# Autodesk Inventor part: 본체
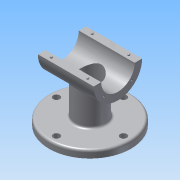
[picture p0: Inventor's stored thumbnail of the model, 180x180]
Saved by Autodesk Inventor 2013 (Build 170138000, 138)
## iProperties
Created: 2015-12
Part Number: 본체
Material: 알루미늄 6061
Document SubType Name: Modeling
Designer: mduedu
Density: 2.71 g/cm^3
Mass: 472.288 g
Surface Area: 460.057 cm^2
Volume: 174.276 cm^3
Author: mduedu
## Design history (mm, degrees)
sketch "스케치1"
  geometry: C1 r 55 at (0, 0); 1 further point
  constraints: 1 centre point, 1 coincident
  dimensions: "d124" = 110 diameter of C1
extrude "돌출1" new body sketch "스케치1" distance "d3" = 10; taper "d4" = 0 deg
sketch "스케치2"
  geometry: C1 r 32.5 at (80, 0); 1 further point
  constraints: 1 centre point, 1 horizontal alignment
  dimensions: "d5" = 65 diameter of C1; "d125" = 80 distance of C1.centre point (0, 0)
extrude "돌출2" join sketch "스케치2" stored distance "d7" = 75; taper "d8" = 0 deg
sketch "스케치3"
  geometry: C1 r 20 at (0, 0); 1 further point
  constraints: 1 centre point, 1 coincident
  dimensions: "d154" = 40 diameter of C1
extrude "돌출3" new body sketch "스케치3" stored distance "d12" = 75; taper "d13" = 0 deg
feature "결합1"
  node "솔리드2"
fillet "모깎기13" dims "d155" = 3
fillet "모깎기7" dims "d41" = 3
hole "구멍2" diameter "d44" = 45; stored, may be unused: countersink angle "d48" = 90 deg, drill point angle "d50" = 118 deg; dims "d42" = 10, "d43" = 10, "d45" = 6, "d46" = 4, "d47" = 2, "d49" = 8
sketch "스케치7" dims "d52" = 26.5
  geometry: L1 (0, 0)-(32.5, 0); L2 (0, 0)-(22.981, 22.981); A1 r 32.5 centre (0, 0) between (32.5, 0) and (22.981, 22.981) reference; 3 further points
  constraints: 4 end point, 2 point on circle, 1 coincident, 1 horizontal, 1 point on line, 3 other
  dimensions: "d51" = 45 deg angle of L2 L1
hole "구멍3" sketch "스케치7" at (18.738, 18.738) diameter "d54" = 2.459; stored, may be unused: countersink angle "d58" = 90 deg, drill point angle "d60" = 118 deg; dims "d55" = 8, "d56" = 4, "d57" = 2, "d59" = 10
sketch "스케치9"
  geometry: L1 (-75, 82.5)-(75, 82.5); L2 (75, 82.5)-(75, 0); L3 (75, 0)-(-75, 0); L4 (-75, 0)-(-75, 82.5); C1 r 32.5 at (0, 0) reference; 2 further points
  constraints: 8 end point, 2 parallel, 1 coincident, 1 horizontal, 1 midpoint, 1 perpendicular
  dimensions: "d71" = 50 distance edge to line of C1 L1; "d116" = 150 distance between parallel lines of L2 L4
extrude "돌출5" cut sketch "스케치9" stored distance "d73" = 0; taper "d74" = 0 deg
node "작업 평면1"
sketch "스케치10"
  geometry: C1 r 15 at (0, 0); 1 further point
  constraints: 1 centre point, 1 coincident
  dimensions: "d156" = 30 diameter of C1
extrude "돌출6" cut sketch "스케치10" stored distance "d78" = 50; taper "d79" = 0 deg
sketch "스케치11"
  geometry: 2 further points
  constraints: 1 coincident
hole "구멍4" sketch "스케치11" at (0, 0) diameter "d81" = 12; stored, may be unused: countersink angle "d85" = 90 deg, drill point angle "d87" = 118 deg; dims "d82" = 8, "d83" = 30, "d84" = 10, "d86" = 10
sketch "스케치12"
  geometry: C1 r 10 at (0, 0); 1 further point
  constraints: 1 centre point, 1 coincident
  dimensions: "d88" = 20 diameter of C1
extrude "돌출7" cut sketch "스케치12" distance "d89" = 10; taper "d90" = 0 deg
chamfer "모따기1" distance "d91" = 1; stored, may be unused: second distance "d92" = 2, angle "d93" = 45 deg
sketch "스케치15"
  geometry: L1 (-75, 55)-(-75, 65) reference; L2 (0, 65)-(0, 55) reference; L3 (-75, 60)-(0, 60); C1 r 1.5 at (-62, 60); 1 further point
  constraints: 2 end point, 2 midpoint, 1 centre point, 1 point on line
  dimensions: "d117" = 3 diameter of C1; "d118" = 13 distance from line of C1.centre L1
extrude "돌출8" join sketch "스케치15" distance "d119" = 1.8; taper "d120" = 0 deg
chamfer "모따기2" distance "d121" = 0.5; stored, may be unused: second distance "d122" = 2, angle "d123" = 45 deg
sketch "스케치18" dims "d141" = 90
  geometry: C1 r 52 at (0, 0) reference; 2 further points
  constraints: 2 vertical alignment, 1 coincident, 2 other
hole "구멍8" sketch "스케치18" at (0, 45) diameter "d142" = 9; stored, may be unused: countersink angle "d146" = 90 deg, drill point angle "d148" = 118 deg; dims "d143" = 6, "d144" = 4, "d145" = 2, "d147" = 8
node "솔리드1"
pattern_circular "원형 패턴1" dims angle "d62" = 360 deg
mirror "대칭3"
mirror "대칭5"
mirror "대칭6"
pattern_circular "원형 패턴2" dims angle "d150" = 360 deg
